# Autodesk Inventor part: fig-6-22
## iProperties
Created: 2005-04
Part Number: fig-6-22
Document SubType Name: Modeling
Designer: CADCIM
Author: CADCIM
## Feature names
1. Extrusion1
2. Extrusion2
3. Extrusion3
